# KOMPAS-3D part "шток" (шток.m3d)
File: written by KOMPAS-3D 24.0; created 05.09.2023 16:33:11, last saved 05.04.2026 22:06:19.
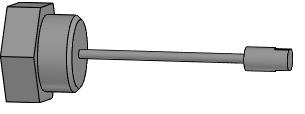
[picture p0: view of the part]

Document properties: Полное имя файла: C:\Users\R2D2\Desktop\ЭИП-1600 Электропневматический позиционер DN.ru — копия\25-50\исходные материалы\шток.m3d

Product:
- Part/product: шток
    Масса: 0.136404

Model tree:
1. Операция без истории:1
2. Эскиз:1  (with: Грань.Операция без истории:1)
3. Элемент выдавливания:1
     Расстояние 2 = 107.1
4. Эскиз:2
5. Элемент выдавливания:2
6. Эскиз:3
7. Элемент вращения:1
     Угол 1 = 360
8. Эскиз:4  (with: Грань.Элемент вращения:1)
9. Элемент выдавливания:3
10. Фаска:1  (with: Ребро.Элемент вращения:1)
     Угол = 45; Длина 1 = 1.5; Длина 2 = 1.5
11. Эскиз:5  (with: Грань.Элемент вращения:1)
12. Элемент выдавливания:4
     Расстояние 2 = 5

Expressions: 8.5+3; 84-v81/2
